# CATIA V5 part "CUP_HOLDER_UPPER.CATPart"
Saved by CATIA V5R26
Part number: CUP_HOLDER_UPPER
Bounding box of the stored display mesh (mm): x -45.5 to 45.5, y -84.5 to 84.5, z -30.5 to 9
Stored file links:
  C:\Users\CAS-\Desktop\Cupholder\Clean_ASM\CUP_HOLDER_UPPER.CATPart
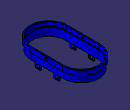
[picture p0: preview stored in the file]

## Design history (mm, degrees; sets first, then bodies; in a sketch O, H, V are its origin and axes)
AxisSystem1: origin (0, 0, 0), X (1, 0, 0), Y (0, 1, 0), Z (0, 0, 1)
Body1 (main body)
  Sketch1 on XY plane of AxisSystem1, origin (0, 0, 0), H (1, 0, 0), V (0, 1, 0)
    line L1 (0, 82) -> (0, -82)
    point P1 (0, 39)
    point P2 (0, -39)
    line L2 (43, 39) -> (43, -39)
    arc A1 centre (0, -39) radius 43 from (43, -39) to (0, -82) cw
    arc A2 centre (0, 39) radius 43 from (0, 82) to (43, 39) cw
    distance L1 L2 = 43
    distance H P2 = 39
    distance H P1 = 39
    coincidence: P1 V, P1 L1, P2 L1
    vertical: L1 V
    tangency: A1 L2, A2 L2
  Pad1: profile Sketch1, direction (0, 0, -1), length 19.25
  Sketch2 on XY plane of AxisSystem1, origin (0, 0, 0), H (1, 0, 0), V (0, 1, 0)
    point P1 (0, 29.75)
    line L1 (0, 29.75) -> (43, 29.75)
    line L2 (43, 29.75) -> (43, 15)
    line L3 (43, 15) -> (0, 15)
    line L4 (0, 15) -> (0, 29.75)
    point P2 (43, 29.75)
    point P3 (43, 15)
    point P4 (0, 15)
    reference projected line E1 (43, -39) -> (43, 39) from Sketch1.L2
    point P5 (0, -15)
    point P6 (43, -15)
    line L5 (43, -15) -> (0, -15)
    point P7 (0, -29.75)
    line L6 (0, -15) -> (0, -29.75)
    point P8 (43, -29.75)
    line L7 (0, -29.75) -> (43, -29.75)
    line L8 (43, -29.75) -> (43, -15)
    distance H L3 = 15
    length L4 = 14.75
    horizontal: L1 H, L3 H
    vertical: L2 V, L4 V
    coincidence: E1 L2, V L4
    symmetry: P4 P5 H, P3 P6 H, L3 L5 H, P1 P7 H, L4 L6 H, P2 P8 H, L1 L7 H, L2 L8 H
  Pad2: profile Sketch2, direction (0, 0, -1), length 30.5
  Draft1: Angle 1, Neutral start face of Pad1, PullDir start face of Pad1, SupportToDraft face of Pad1 from Sketch1.L2
  Draft2: Angle 2.5, Neutral end face of Pad1, PullDir end face of Pad1, SupportToDraft (face of Pad2 from Sketch2.L7; face of Pad2 from Sketch2.L3; face of Pad2 from Sketch2.L5; face of Pad2 from Sketch2.L1)
  Fillet1: radius 2, on edge [end face of Pad1 | face of Pad2 from Sketch2.L1]; edge [face of Pad2 from Sketch2.L1 | end face of Pad2]; edge [face of Pad2 from Sketch2.L3 | end face of Pad2]; edge [end face of Pad1 | face of Pad2 from Sketch2.L3]; edge [face of Pad2 from Sketch2.L5 | end face of Pad2]; edge [face of Pad2 from Sketch2.L7 | end face of Pad2]; edge [end face of Pad1 | face of Pad2 from Sketch2.L7]; edge [end face of Pad1 | face of Pad2 from Sketch2.L5]
  Shell1: ExtOffset 0, Face (end face of Pad1; face of Pad2; face of Pad2), IntOffset 2.9
  Sketch3 on XY plane of AxisSystem1, origin (0, 0, 0), H (1, 0, 0), V (0, 1, 0)
    line L1 (0, 35) -> (41.25, 35)
    line L2 (41.25, 35) -> (41.25, -35)
    line L3 (41.25, -35) -> (0, -35)
    line L4 (0, -35) -> (0, 35)
    reference projected line E1 (43, -39) -> (43, 39) from Sketch1.L2
    reference projected line E2 (0, 82) -> (0, -82) from Sketch1.L1
    distance E1 L2 = 1.75
    distance H L1 = 35
    distance H L3 = 35
    horizontal: L1 H, L3 H
    vertical: L2 V, L4 V
    coincidence: L4 E2
  Pocket1: profile Sketch3, direction (0, 0, -1), length 66, opposite side up to end face of Pad1
  Sketch4 on XY plane of AxisSystem1, origin (0, 0, 0), H (1, 0, 0), V (0, 1, 0)
    projected arc E1 centre (0, -39) radius 43 from (0, -82) to (43, -39) ccw from edge [face of Pad1 from Sketch1.A1 | start face of Pad1]
    projected line E2 (43, -39) -> (43, 39) from edge [face of Pad1 from Sketch1.L2 | start face of Pad1]
    projected arc E3 centre (0, 39) radius 43 from (43, 39) to (0, 82) ccw from edge [face of Pad1 from Sketch1.A2 | start face of Pad1]
  Pad3: profile Sketch4, direction (0, 0, 1), length 9, opposite side length 2, thin wall 0.5, second thickness 2.5
  Sketch5 on face of Pad3, origin (45.5, 1.7034, 2.6966), H (0, 1, 0), V (0, 0, 1)
    point P1 (-1.7034, 1.3034)
    reference projected line E1 (-40.7034, 6.3034) -> (37.2966, 6.3034) from edge [face of Pad3 | end face of Pad3]
    reference intersected line E2 through (-1.7034, 0) direction (0, 1) from ZX plane of AxisSystem1
    distance P1 E1 = 5
    coincidence: P1 E2
  Hole1: placed by Sketch5, at (45.5, 0, 4) direction (-1, 0, 0), diameter 4.6, through (limit type 6), countersink depth 1.5, countersink angle 90
  Mirror1: of the body so far, about ZX plane of AxisSystem1
  Sketch6 on YZ plane of AxisSystem1, origin (0, 0, 0), H (0, 1, 0), V (0, 0, 1)
    line L1 (19, -28.26) -> (25.75, -28.26)
    line L2 (19, -20.76) -> (19, -28.26)
    line L3 (25.75, -20.76) -> (19, -20.76)
    line L4 (25.75, -28.26) -> (25.75, -20.76)
    point P1 (25.75, -20.76)
    point P2 (19, -20.76)
    point P3 (19, -28.26)
    point P4 (25.75, -28.26)
    reference projected line E1 (27.3442, -30.5) -> (17.4058, -30.5) from edge [face of Pad2 | end face of Pad2]
    construction line L5 (22.375, -30.5) -> (22.375, -28.26)
    point P7 (22.375, -30.5)
    point P8 (22.375, -28.26)
    point P9 (19, -28.26)
    point P10 (19, -28.26)
    point P11 (25.75, -28.26)
    point P12 (25.75, -28.26)
    point P13 (25.75, -20.76)
    point P14 (19, -20.76)
    point P15 (-25.75, -28.26)
    point P16 (-19, -28.26)
    line L6 (-19, -28.26) -> (-25.75, -28.26)
    point P17 (-19, -28.26)
    point P18 (-19, -20.76)
    line L7 (-19, -20.76) -> (-19, -28.26)
    point P19 (-25.75, -20.76)
    line L8 (-25.75, -20.76) -> (-19, -20.76)
    point P20 (-25.75, -28.26)
    line L9 (-25.75, -28.26) -> (-25.75, -20.76)
    distance E1 L1 = 2.24
    distance L1 L3 = 7.5
    distance L5 L4 = 3.375
    distance L5 L2 = 3.375
    midpoint: P7 E1, P8 L1
    vertical: L5 V, L4 V
    coincidence: L3 P1, L4 P1, L2 P2, L3 P2, L2 P3, L1 P3, L4 P4, L1 P4, P12 P11, P9 P3
    symmetry: P12 P15 V, P10 P16 V, L1 L6 V, P9 P17 V, P14 P18 V, L2 L7 V, P13 P19 V, L3 L8 V, P11 P20 V, L4 L9 V
  Pocket2: profile Sketch6, direction (1, 0, 0), through (limit type 3)
  Mirror2: of the body so far, about YZ plane of AxisSystem1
